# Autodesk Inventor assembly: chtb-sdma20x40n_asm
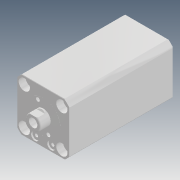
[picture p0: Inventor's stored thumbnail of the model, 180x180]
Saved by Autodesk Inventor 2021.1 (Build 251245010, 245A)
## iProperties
Created: 2018-05
Part Number: chtb-sdma20x40n_asm
Description: STEP AP214
Document SubType Name: Assembly
Designer: user
Title: chtb-sdma20x40n_asm.STEP
Revision Number: ÈÎºÎ
Sending System: SolidWorks 2016
Preprocessor: SwSTEP 2.0
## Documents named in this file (5)
- D:\Vault_2016\Projekty\Clamptek\Hydraulic\CHTB\CHTB-20\Inventor\CHTB-SDMA20x40N\chtb-sdma20x40n_asm.iam
- D:\Vault_2016\Projekty\Clamptek\Hydraulic\CHTB\CHTB-20\Inventor\CHTB-SDMA20x40N\CHTB-SDMA20X40NBT.ipt
- D:\Vault_2016\Projekty\Clamptek\Hydraulic\CHTB\CHTB-20\Inventor\CHTB-SDMA20x40N\CHTB-SDMA20X40NHSG.ipt
- D:\Vault_2016\Projekty\Clamptek\Hydraulic\CHTB\CHTB-20\Inventor\CHTB-SDMA20x40N\QG_3.ipt
- D:\Vault_2016\Projekty\Clamptek\Hydraulic\CHTB\CHTB-20\Inventor\CHTB-SDMA20x40N\socket set screw flat point_iso_ISO 4026 - M5 x 5-N.ipt
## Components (5 placed, 5 different names)
1. CHTB-SDMA20X40NBT_1
2. CHTB-SDMA20X40NHSG_2
3. QG_3_3
4. socket set screw flat point_iso_ISO 4026 - M5 x 5-N_4
5. socket set screw flat point_iso_ISO 4026 - M5 x 5-N_5
